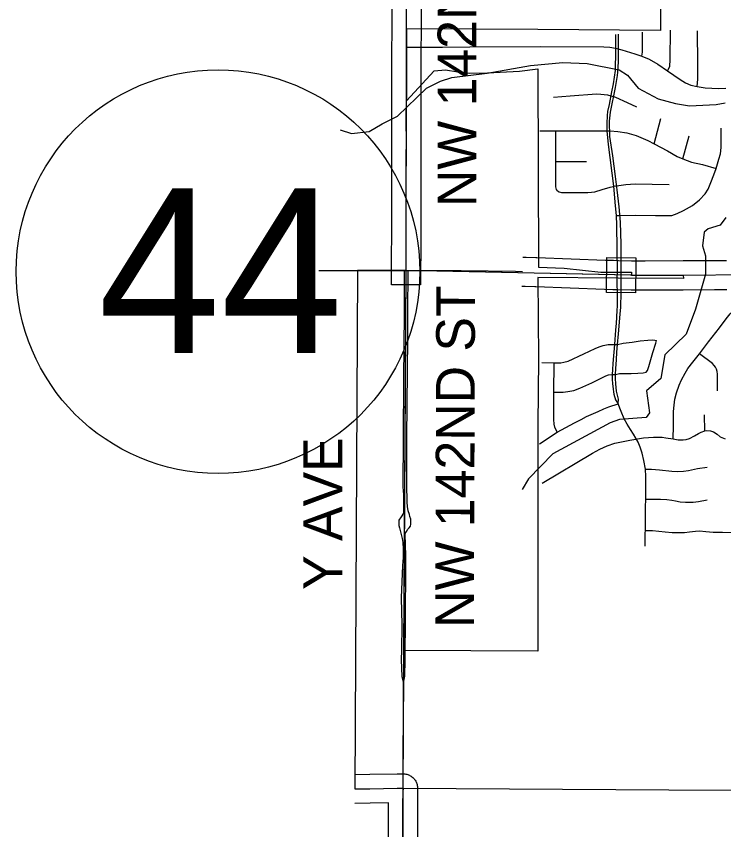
# Model space of a CAD drawing. Extents: x -1403959 to 81668, y -1400582 to 11018.
# Drawn here: x 6140.2 to 6281.6, y 8808.1 to 8970.6 of the extents above; entities that cross this region are included whole.
import ezdxf

# ---------------------------------------------------------------- set-up
doc = ezdxf.new("R2010")
doc.units = 0
for name, color, linetype in [('tdCiCityDivCarto', 7, 'Continuous'), ('tdCiCoBndryTxt', 7, 'Continuous'), ('tdCiMapFrame', 7, 'Continuous'), ('tdCiRRCL', 7, 'Continuous'), ('tdCiRROwnerTxt', 7, 'Continuous'), ('tdCiSectLine', 7, 'Continuous'), ('tdCiSectNmbr', 7, 'Continuous'), ('tdCiSectTwpRng', 7, 'Continuous'), ('tdCiUABTitleFrame', 7, 'Continuous'), ('tdCoCityStreetMajor', 7, 'Continuous'), ('tdCoClipBndry', 7, 'Continuous'), ('tdCoDivCarto', 7, 'Continuous'), ('tdCoSecRteCL', 7, 'Continuous'), ('tdCoSectNmbr', 7, 'Continuous'), ('tdCoSurfAsphalt', 7, 'Continuous'), ('tdCoSurfBitum', 7, 'Continuous'), ('tdCoSurfGravelUnbanded', 7, 'Continuous')]:
    doc.layers.add(name, color=color, linetype=linetype)

msp = doc.modelspace()

# ---------------------------------------------------------------- linework, layer by layer
at = {"layer": 'tdCiCityDivCarto'}
for points in [[(6217.88, 8843.96), (6217.94, 8848.75), (6218.02, 8862.17), (6217.98, 8865.57), (6217.88, 8866.54), (6217.92, 8867.26), (6218.14, 8867.66), (6218.42, 8868.09), (6218.67, 8868.39), (6218.93, 8868.73), (6219.03, 8869.11), (6219.03, 8869.62), (6218.99, 8870.1), (6218.85, 8870.62), (6218.75, 8871.07), (6218.51, 8871.79), (6218.34, 8872.65), (6218.28, 8873.5), (6218.2, 8877.06), (6218.24, 8886.3), (6218.4, 8906.34), (6218.4, 8911.21), (6218.49, 8919.84)], [(6217.88, 8843.84), (6217.88, 8843.96)]]:
    msp.add_lwpolyline(points, dxfattribs=at)
at = {"layer": 'tdCiCoBndryTxt'}
for points in [[(6218.16, 8968.12), (6218.16, 8968.65), (6218.16, 8972.32), (6218.16, 8974.83), (6218.12, 8980.97), (6218.12, 8985.41), (6218.12, 8987.17), (6218.11, 8993.26), (6218.12, 8994.65), (6218.15, 8999.22), (6218.15, 9004.1), (6218.15, 9005.2), (6218.16, 9011.35), (6218.16, 9012.41), (6218.17, 9016.46)], [(6218.13, 8953.72), (6218.14, 8955.91), (6218.15, 8956.66), (6218.13, 8962.61), (6218.16, 8968.12)], [(6218.06, 8919.84), (6218.08, 8923.63), (6218.11, 8925.94), (6218.11, 8931.51), (6218.11, 8933.58), (6218.12, 8937.68), (6218.13, 8943.58), (6218.13, 8944.9), (6218.12, 8950.24), (6218.13, 8953.72)]]:
    msp.add_lwpolyline(points, dxfattribs=at)
at = {"layer": 'tdCiMapFrame'}
for points in [[(6207.82, 8816.22), (6208.45, 8816.23), (6210.86, 8816.26), (6216.31, 8816.36), (6217.47, 8816.34)], [(6217.33, 8767.82), (6217.33, 8769.97), (6217.33, 8775.77), (6217.32, 8781.92), (6217.36, 8787.87), (6217.37, 8794.15), (6217.42, 8800.49), (6217.43, 8806.36), (6217.44, 8812.39), (6217.47, 8816.34)]]:
    msp.add_lwpolyline(points, dxfattribs=at)
at = {"layer": 'tdCiRRCL'}
msp.add_line((6208.35, 8919.79), (6207.82, 8816.22), dxfattribs=at)
for points in [[(6268.66, 9016.57), (6268.92, 8967.75), (6244.42, 8967.94), (6218.16, 8968.12), (6218.13, 8962.61), (6218.14, 8955.91), (6218.13, 8953.72), (6223.68, 8959.7), (6225.94, 8959.87), (6228.42, 8959.48), (6230.74, 8959.25), (6234.35, 8959.31), (6236.9, 8959.42), (6240.74, 8959.65), (6244.43, 8960.1), (6244.51, 8920.45), (6249.67, 8920.28), (6256.99, 8919.46), (6263.12, 8919.45), (6263.12, 8918.84), (6273.46, 8918.87), (6273.48, 8918.23), (6260.47, 8918.3), (6244.42, 8918.39), (6244.51, 8902.12), (6244.42, 8888.98), (6244.42, 8843.77), (6217.62, 8843.86), (6218.06, 8919.84), (6208.35, 8919.79)], [(6207.82, 8816.22), (6208.45, 8816.23), (6210.86, 8816.26), (6216.31, 8816.36), (6217.47, 8816.34), (6217.45, 8815.61), (6217.44, 8812.39), (6217.43, 8806.36)]]:
    msp.add_lwpolyline(points, dxfattribs=at)
at = {"layer": 'tdCiRROwnerTxt'}
for points in [[(6261.05, 8918.28), (6261.05, 8918.31)], [(6261.07, 8919.43), (6261.07, 8919.45)]]:
    msp.add_lwpolyline(points, dxfattribs=at)
at = {"layer": 'tdCiSectLine'}
for points in [[(6221.06, 8974.83), (6221.06, 8968.65), (6221.06, 8968.63), (6221.04, 8962.61), (6221.05, 8956.67), (6221.05, 8956.66), (6221.05, 8956.65), (6221.02, 8950.24), (6221.04, 8943.58), (6221.04, 8943.58), (6221.04, 8943.57), (6221.01, 8931.5), (6221.01, 8925.94), (6221.01, 8925.91), (6220.99, 8923.6), (6220.96, 8919.82), (6220.94, 8916.92), (6215.13, 8916.96), (6215.15, 8919.86), (6215.18, 8923.65), (6215.18, 8923.66), (6215.21, 8925.95), (6215.21, 8931.51), (6215.21, 8931.51), (6215.23, 8943.58), (6215.22, 8950.24), (6215.22, 8950.24), (6215.22, 8950.25), (6215.24, 8956.66), (6215.23, 8962.6), (6215.23, 8962.61), (6215.23, 8962.62), (6215.26, 8968.65), (6215.26, 8974.82)], [(6263.92, 8915.35), (6258.12, 8915.42), (6258.15, 8918.08), (6258.17, 8919.47), (6258.17, 8919.48), (6258.2, 8922.38), (6264, 8922.32), (6263.99, 8921.18), (6263.99, 8921.18), (6263.96, 8918.28), (6263.96, 8918.25), (6263.95, 8918.01), (6263.94, 8916.5), (6263.94, 8916.5), (6263.92, 8915.35)], [(6207.84, 8819.12), (6210.81, 8819.16), (6216.26, 8819.26), (6216.31, 8819.26), (6216.35, 8819.26), (6217.51, 8819.24), (6217.66, 8819.24), (6217.85, 8819.22), (6218.04, 8819.19), (6218.22, 8819.15), (6218.41, 8819.09), (6218.58, 8819.02), (6218.76, 8818.94), (6218.92, 8818.86), (6219.09, 8818.75), (6219.24, 8818.64), (6219.39, 8818.52), (6219.53, 8818.39), (6219.66, 8818.26), (6219.78, 8818.11), (6219.89, 8817.95), (6219.99, 8817.79), (6220.08, 8817.63), (6220.15, 8817.45), (6220.22, 8817.27), (6220.28, 8817.09), (6220.32, 8816.91), (6220.35, 8816.72), (6220.37, 8816.53), (6220.38, 8816.34), (6220.38, 8816.32), (6220.34, 8812.38), (6220.32, 8800.49)], [(6214.52, 8800.51), (6214.54, 8812.4), (6214.54, 8812.41), (6214.55, 8813.42), (6210.91, 8813.36), (6210.9, 8813.36), (6207.81, 8813.32)]]:
    msp.add_lwpolyline(points, dxfattribs=at)
at = {"layer": 'tdCiSectNmbr'}
for points in [[(6217.66, 8919.84), (6217.68, 8911.17), (6217.56, 8898.19), (6217.48, 8886.26), (6217.4, 8876.56), (6217.54, 8874.95), (6217.56, 8873.14), (6217.58, 8871.33), (6217.06, 8870.56), (6216.65, 8869.9), (6216.61, 8869.41), (6216.65, 8868.83), (6216.77, 8868.39), (6217.28, 8866.24), (6217.4, 8865.43), (6217.48, 8864.2), (6217.52, 8862.45), (6217.36, 8860.86), (6217.1, 8854.4), (6217.22, 8849.01), (6217.15, 8843.97)], [(6217.15, 8843.97), (6217.12, 8842.01), (6217.22, 8838.65), (6217.55, 8837.44)], [(6217.55, 8837.44), (6217.8, 8838.77), (6217.86, 8841.93), (6217.88, 8843.79)], [(6217.88, 8843.83), (6217.88, 8843.84)], [(6217.88, 8843.79), (6217.88, 8843.83)], [(6217.88, 8843.83), (6217.88, 8843.83)], [(6217.47, 8816.34), (6217.49, 8822.75), (6217.49, 8823.97), (6217.53, 8829.87), (6217.54, 8836.14), (6217.55, 8837.44)], [(6217.47, 8816.34), (6270.56, 8816.04), (6311.92, 8816)]]:
    msp.add_lwpolyline(points, dxfattribs=at)
at = {"layer": 'tdCiSectTwpRng'}
for points in [[(6261.07, 8919.45), (6261.04, 8925.09), (6260.95, 8929.46), (6260.68, 8932.53), (6260.23, 8935.95), (6259.9, 8938.57), (6259.37, 8942.71), (6258.77, 8946.6), (6258.72, 8949.66), (6258.93, 8951.42), (6259.9, 8956.35), (6260.31, 8958.74), (6260.41, 8959.44), (6260.49, 8961.52), (6260.55, 8967.05)], [(6265.21, 8962.63), (6265.33, 8963.44), (6265.32, 8967.44)], [(6270.34, 8959.71), (6270.76, 8960.55), (6270.84, 8961.96), (6270.92, 8967.82)], [(6276.22, 8956.59), (6276.35, 8958.05), (6276.35, 8961.12), (6276.31, 8967.72)], [(6259.91, 8966.97), (6259.91, 8962.46), (6259.87, 8961.01), (6259.83, 8959.79), (6259.45, 8957.1), (6259.12, 8955.49), (6258.63, 8952.98), (6258.32, 8951.56), (6258.23, 8950.74), (6258.18, 8949.18), (6258.16, 8947.73), (6258.45, 8945.01), (6259.51, 8936.62), (6259.88, 8932.75), (6260.07, 8930.77), (6260.15, 8928.89), (6260.23, 8919.45)], [(6218.14, 8964.45), (6225.35, 8964.44), (6230.81, 8964.46), (6244.88, 8964.53), (6257.58, 8964.51), (6258.81, 8964.44), (6259.91, 8964.25), (6261.21, 8963.89), (6263.78, 8963.09), (6265.21, 8962.63), (6266.63, 8962.03), (6268.35, 8961.06), (6270.34, 8959.71), (6272.82, 8957.94), (6273.94, 8957.29), (6275.01, 8956.86), (6276.22, 8956.59), (6277.87, 8956.27), (6280.53, 8956.19), (6281.99, 8956.21)], [(6247.52, 8954.46), (6250.85, 8954.7), (6256.11, 8955.09), (6257.01, 8955.05), (6258.31, 8954.89), (6259.95, 8954.43), (6262.27, 8953.37), (6264.09, 8952.51)], [(6264.09, 8952.51), (6264.09, 8952.51)], [(6267.67, 8945.12), (6269.01, 8950.18)], [(6244.81, 8947.72), (6247.99, 8947.71), (6258.16, 8947.73), (6258.84, 8947.72), (6260.37, 8947.6), (6262.17, 8947.3), (6264.06, 8946.76), (6266.38, 8945.76), (6267.67, 8945.12), (6270.34, 8943.68), (6272.26, 8942.59), (6273.39, 8942.09), (6275.11, 8941.48), (6277.31, 8941), (6280.05, 8940.17)], [(6248.36, 8935.71), (6248.14, 8936), (6248.01, 8936.52), (6247.99, 8947.71)], [(6280.05, 8940.17), (6280.59, 8942.02), (6280.91, 8943.08), (6281.07, 8944.39), (6281.07, 8946.6), (6281.07, 8948.22)], [(6273.39, 8942.09), (6274.64, 8946.68)], [(6248, 8941.56), (6254.12, 8941.59)], [(6260.07, 8930.77), (6260.82, 8930.82), (6263.88, 8930.84), (6267.9, 8930.77), (6269.97, 8930.77), (6271.19, 8930.82), (6272.24, 8931.17), (6273.51, 8931.76), (6275.28, 8932.82), (6276.74, 8933.89), (6277.82, 8935.13), (6278.41, 8936.07), (6278.98, 8937.37), (6279.6, 8938.93), (6280.05, 8940.17)], [(6248.36, 8935.71), (6248.66, 8935.49), (6249.13, 8935.42), (6254.37, 8935.42), (6255.13, 8935.45), (6255.8, 8935.54), (6257.29, 8935.99), (6258.83, 8936.47), (6259.44, 8936.6)], [(6259.44, 8936.6), (6259.51, 8936.62)], [(6259.51, 8936.62), (6260.13, 8936.7), (6261.99, 8937), (6263.85, 8937.14), (6270.63, 8936.98)], [(6260.14, 8895.67), (6259.97, 8897.17), (6259.92, 8898.23), (6259.91, 8899.03), (6259.97, 8900.25), (6260.1, 8901.93), (6260.21, 8903.49), (6260.33, 8905.04), (6260.51, 8907.16), (6260.86, 8911.09), (6260.97, 8912.45), (6260.99, 8913.27), (6261.03, 8914.6), (6261.03, 8915.56), (6261.04, 8918), (6261.05, 8918.28)], [(6260.2, 8918.3), (6260.22, 8918.05)], [(6260.22, 8918.05), (6260.27, 8914.47), (6260.27, 8913.51), (6260.27, 8912.63), (6260.21, 8911.92), (6260.12, 8910.39), (6260.04, 8909.3), (6259.92, 8907.87), (6259.8, 8906.03), (6259.72, 8905.04), (6259.4, 8901.21), (6259.32, 8900.03), (6259.24, 8899.03), (6259.26, 8898.05), (6259.33, 8897.2), (6259.44, 8896.06), (6259.53, 8895.55)], [(6271.48, 8886.15), (6271.51, 8888.74), (6271.53, 8891.64), (6271.62, 8892.88), (6271.81, 8894.08), (6272.12, 8895.38), (6272.62, 8896.9), (6273.08, 8897.96), (6273.82, 8899.28), (6274.4, 8900.2), (6275.39, 8901.51), (6276.73, 8903.16), (6278.52, 8905.57), (6280.68, 8908.36), (6282.06, 8910.15), (6282.85, 8911.17), (6283.35, 8911.76), (6284.09, 8912.41), (6284.86, 8912.94), (6286.03, 8913.55), (6287.83, 8914.38), (6289.26, 8915.13), (6290.51, 8916)], [(6260.33, 8905.04), (6261.44, 8905.29), (6263.28, 8905.49), (6264.87, 8905.76), (6266.39, 8905.91), (6267.31, 8905.96), (6267.79, 8905.91), (6268.13, 8905.8)], [(6266.05, 8899.52), (6266.3, 8899.83), (6266.57, 8900.65), (6267.41, 8903.4), (6268, 8905.29), (6268.13, 8905.8)], [(6245.18, 8901.41), (6247.65, 8901.36), (6249.03, 8901.36), (6249.63, 8901.46), (6250.44, 8901.68), (6253.61, 8903.16), (6255.86, 8904.25), (6256.65, 8904.56), (6257.45, 8904.82), (6258.48, 8904.99), (6259.72, 8905.04), (6260.04, 8905.04)], [(6260.04, 8905.04), (6260.33, 8905.04)], [(6280.34, 8895.79), (6280.28, 8899.06), (6280.23, 8899.62), (6280.09, 8900.11), (6279.91, 8900.46), (6279.67, 8900.84), (6279.3, 8901.2), (6276.73, 8903.16)], [(6247.6, 8890.98), (6247.63, 8895.48), (6247.65, 8901.3)], [(6247.65, 8901.3), (6247.65, 8901.36)], [(6247.63, 8895.48), (6249.47, 8895.5), (6250.39, 8895.6), (6251.57, 8895.84), (6252.78, 8896.28), (6255.19, 8897.39), (6258.01, 8898.77), (6258.55, 8898.93), (6259.24, 8899.03), (6259.84, 8899.03)], [(6259.84, 8899.03), (6259.91, 8899.03)], [(6259.91, 8899.03), (6260.74, 8899.19), (6263.07, 8899.25), (6264.4, 8899.31), (6265.44, 8899.36), (6266.05, 8899.52)], [(6259.53, 8895.55), (6259.62, 8895.08), (6259.92, 8893.96), (6260.45, 8893.15)], [(6260.46, 8893.19), (6260.49, 8894.1), (6260.14, 8895.67)], [(6244.72, 8885.16), (6248.27, 8887.48), (6250.85, 8888.89), (6251.76, 8889.39), (6253.05, 8890.05), (6254.15, 8890.61), (6255.07, 8891.04), (6256.45, 8891.66), (6257.61, 8892.18), (6258.61, 8892.57), (6260.45, 8893.15)], [(6261.03, 8891.62), (6260.45, 8893.15), (6260.46, 8893.19)], [(6248.27, 8887.48), (6247.78, 8888.51), (6247.64, 8889.07), (6247.58, 8890.02), (6247.6, 8890.94), (6247.6, 8890.98)], [(6265.83, 8864.75), (6266, 8876.21), (6266.01, 8878.63), (6265.9, 8880.14), (6265.6, 8881.82), (6265.26, 8883.29), (6264.88, 8884.49), (6264.47, 8885.53), (6263.5, 8887.09), (6262.93, 8888.05), (6262.27, 8889.1), (6261.67, 8890.18), (6261.03, 8891.62)], [(6277.76, 8887.79), (6277.71, 8890.99)], [(6245.26, 8877.34), (6255.31, 8883.29), (6256.8, 8884.12), (6258.24, 8884.74), (6259.81, 8885.3), (6262.77, 8885.92), (6265.54, 8886.36), (6267.5, 8886.52), (6268.6, 8886.5), (6269.26, 8886.48), (6269.98, 8886.36), (6271.48, 8886.15), (6272.47, 8885.97), (6273.43, 8885.97), (6274.04, 8886.04), (6274.7, 8886.26), (6275.74, 8886.77), (6276.49, 8887.21), (6277.06, 8887.52), (6277.76, 8887.79), (6278.19, 8887.82), (6278.88, 8887.74), (6279.48, 8887.56), (6280.22, 8887.1), (6280.82, 8886.6), (6281.81, 8886.17)], [(6265.9, 8880.14), (6267.09, 8880.08), (6268.71, 8879.95), (6271.21, 8879.69), (6272.38, 8879.66), (6273.48, 8879.73), (6274.48, 8879.83), (6276.34, 8880.22), (6278.22, 8880.53)], [(6278.22, 8880.53), (6278.22, 8880.53)], [(6265.97, 8874.1), (6267.23, 8874.1), (6268.89, 8874.1), (6270.18, 8874.02), (6271.16, 8873.93), (6271.93, 8873.77), (6272.87, 8873.57), (6273.89, 8873.51), (6275.42, 8873.52), (6276.49, 8873.66), (6278.21, 8873.96)], [(6281.3, 8867.53), (6283.95, 8867.48), (6287.66, 8867.45), (6288.37, 8867.63), (6289.04, 8867.97), (6289.55, 8868.5)], [(6265.88, 8867.88), (6267.33, 8867.85), (6268.61, 8867.71), (6269.85, 8867.56), (6271.23, 8867.43), (6272.35, 8867.42), (6273.68, 8867.46), (6274.74, 8867.56), (6275.91, 8867.72), (6276.72, 8867.76), (6277.99, 8867.68), (6279.47, 8867.54), (6281.3, 8867.53)]]:
    msp.add_lwpolyline(points, dxfattribs=at)
at = {"layer": 'tdCiUABTitleFrame'}
for points in [[(6260.23, 8919.45), (6260.2, 8918.3)], [(6261.05, 8918.31), (6261.07, 8919.43)]]:
    msp.add_lwpolyline(points, dxfattribs=at)
at = {"layer": 'tdCoCityStreetMajor'}
for points in [[(6208.35, 8919.82), (6215.18, 8919.84)], [(6220.98, 8919.78), (6263.09, 8918.91)]]:
    msp.add_lwpolyline(points, dxfattribs=at)
at = {"layer": 'tdCoClipBndry'}
for points in [[(6778.71, 10085.37), (6705.52, 10085.58), (6607.92, 10086.06), (6510.34, 10086.5), (6412.84, 10087.26), (6315.56, 10087.31), (6215.78, 10087.65), (6215.21, 10012.23), (6215.81, 9994.41), (6217.04, 9970.57), (6217.41, 9896.62), (6217.06, 9848.03), (6217.62, 9799.5), (6216.78, 9702.88), (6218.33, 9606.68), (6218.57, 9510.16), (6218.52, 9404.76), (6218.61, 9307.34), (6218.13, 9211.25), (6218.14, 9113.22), (6218.14, 9016.46), (6218.02, 8919.84), (6217.44, 8816.34), (6216.99, 8719.3)], [(6218.02, 8919.84), (6266.12, 8918.85), (6293.75, 8918.97)]]:
    msp.add_lwpolyline(points, dxfattribs=at)
at = {"layer": 'tdCoDivCarto'}
for points in [[(6241.43, 8922.49), (6242.08, 8922.46), (6244.01, 8922.39), (6244.2, 8922.39), (6257.93, 8921.88), (6259.54, 8921.84), (6260.51, 8921.81), (6263.12, 8921.74), (6265.88, 8921.75), (6273.42, 8921.77), (6279.69, 8921.8), (6279.94, 8921.8), (6282.09, 8921.81), (6282.12, 8921.81)], [(6241.22, 8916.69), (6241.86, 8916.66), (6243.79, 8916.59), (6243.99, 8916.59), (6257.74, 8916.08), (6259.39, 8916.03), (6260.35, 8916.01), (6263.05, 8915.94), (6265.9, 8915.95), (6273.44, 8915.97), (6279.72, 8915.99), (6279.96, 8915.99), (6282.11, 8916), (6282.15, 8916)]]:
    msp.add_lwpolyline(points, dxfattribs=at)
at = {"layer": 'tdCoSecRteCL'}
msp.add_lwpolyline([(6200.62, 8919.78), (6229.09, 8919.82), (6239.97, 8919.64), (6241.33, 8919.59)], dxfattribs=at)
at = {"layer": 'tdCoSurfAsphalt'}
msp.add_circle((6180.49, 8919.58), 40.33, dxfattribs=at)
at = {"layer": 'tdCoSurfBitum'}
for points in [[(6204.88, 8947.94), (6207.17, 8947.15), (6210.69, 8947.59), (6213.29, 8949.11), (6216.35, 8950.62), (6222.17, 8956.25), (6224.93, 8957.61), (6227.22, 8958.37), (6234.25, 8959.26), (6242.96, 8960.75), (6249.37, 8961.34), (6254.26, 8961.17), (6260.67, 8959.92), (6262.34, 8958.85), (6264.47, 8956.24), (6268.43, 8954.09), (6271.94, 8953.16), (6274.69, 8952.69), (6280.04, 8952.98), (6281.87, 8953.28)], [(6281.94, 8930.38), (6280.87, 8928.85), (6278.42, 8928.1), (6277.66, 8927.49), (6277.34, 8924.74), (6277.94, 8922.76), (6277.93, 8919.09), (6275.92, 8912.08), (6274.07, 8907.05), (6269.78, 8902.94), (6269, 8898.21), (6266.09, 8895.78), (6266.69, 8891.35), (6266.07, 8890.44), (6260.72, 8890), (6258.89, 8889.39), (6247.41, 8883.18), (6242.51, 8878.16), (6241.28, 8876.02)]]:
    msp.add_lwpolyline(points, dxfattribs=at)

# ---------------------------------------------------------------- texts
at = {"layer": 'tdCoSectNmbr'}
for rotation, p in [(90, (6232.11, 8932.48)), (89.7962, (6231.62, 8848.39))]:
    msp.add_text('NW 142ND ST', height=7.7382, rotation=rotation, dxfattribs=at).set_placement(p)
at = {"layer": 'tdCoSurfAsphalt'}
msp.add_text('44', height=32.887, dxfattribs=at).set_placement((6156.53, 8903.35))
at = {"layer": 'tdCoSurfGravelUnbanded'}
msp.add_text('Y AVE', height=7.738, rotation=90, dxfattribs=at).set_placement((6205.3, 8855.99))

doc.saveas('drawing.dxf')
